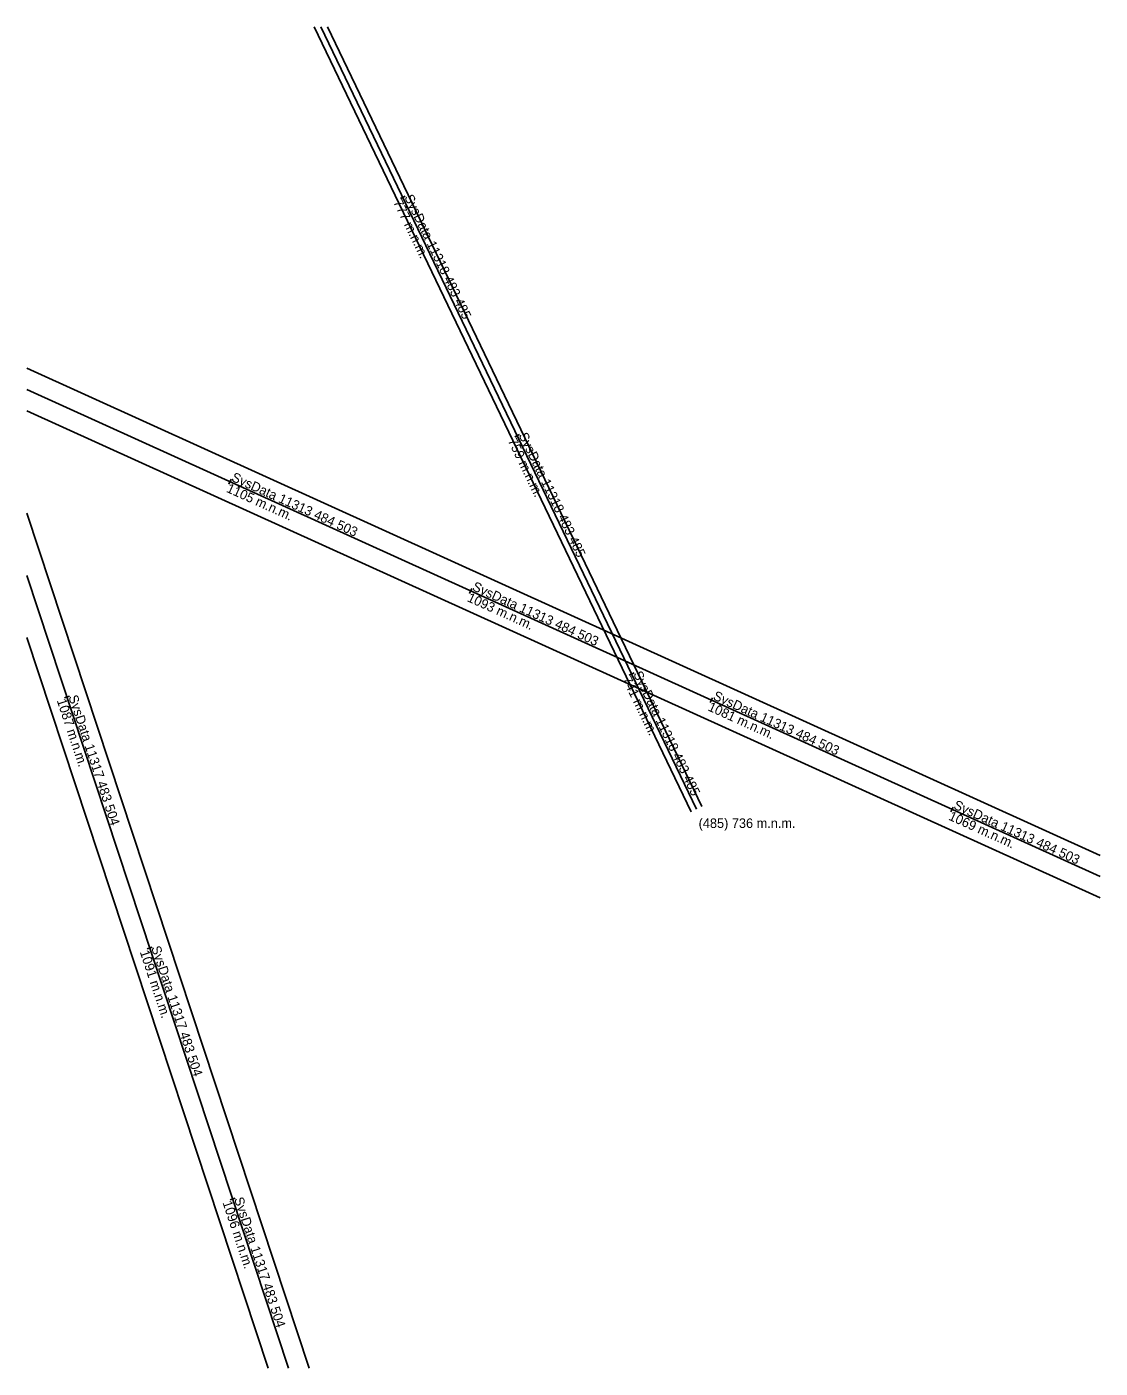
# Model space of a CAD drawing. Extents: x -650309 to -649903, y -983739 to -983231.
import ezdxf

# ---------------------------------------------------------------- set-up
doc = ezdxf.new("R2010")
doc.units = 0
doc.layers.add('Vrstva 1', color=7, linetype='Continuous')

msp = doc.modelspace()

# ---------------------------------------------------------------- linework, layer by layer
at = {"layer": 'Vrstva 1'}
for p, q in [((-650200.49, -983231.28), (-650057.91, -983528.17)), ((-650197.97, -983231.28), (-650055.86, -983527.19)), ((-650195.45, -983231.28), (-650053.81, -983526.21)), ((-650167.89, -983296.23), (-650166.08, -983295.37)), ((-650309.21, -983360.46), (-649903.14, -983544.72)), ((-650309.21, -983368.47), (-649903.14, -983552.74)), ((-650309.21, -983376.49), (-649903.14, -983560.75)), ((-650124.59, -983386.38), (-650122.79, -983385.51)), ((-650231.94, -983402.44), (-650232.77, -983404.26)), ((-650309.21, -983415.27), (-650202.45, -983738.66)), ((-650309.21, -983438.78), (-650210.21, -983738.66)), ((-650140.88, -983443.76), (-650141.71, -983445.58)), ((-650309.21, -983462.28), (-650217.97, -983738.66)), ((-650081.3, -983476.52), (-650079.5, -983475.66)), ((-650294.99, -983485.05), (-650293.09, -983484.42)), ((-650049.82, -983485.08), (-650050.64, -983486.9)), ((-650055.86, -983527.19), (-650055.86, -983527.19)), ((-649958.75, -983526.4), (-649959.58, -983528.23)), ((-650263.64, -983580.01), (-650261.74, -983579.38)), ((-650232.29, -983674.97), (-650230.39, -983674.34))]:
    msp.add_line(p, q, dxfattribs=at)

# ---------------------------------------------------------------- texts
for s, rotation, p in [('777 m.n.m.', 295.6525, (-650170.66, -983297.61)), ('SysData 11318 483 485', 295.6525, (-650166.47, -983295.71)), ('759 m.n.m.', 295.6525, (-650127.33, -983387.85)), ('SysData 11318 483 485', 295.6525, (-650123.22, -983385.77)), ('SysData 11313 484 503', 335.5926, (-650232.11, -983402.91)), ('1105 m.n.m.', 335.5926, (-650233.98, -983407.11)), ('SysData 11313 484 503', 335.5926, (-650140.98, -983444.26)), ('1093 m.n.m.', 335.5926, (-650142.89, -983448.45)), ('741 m.n.m.', 295.6525, (-650084.02, -983478.03)), ('SysData 11318 483 485', 295.6525, (-650079.89, -983476.01)), ('SysData 11317 483 504', 288.2703, (-650293.53, -983484.69)), ('SysData 11313 484 503', 335.5926, (-650049.89, -983485.6)), ('1087 m.n.m.', 288.2703, (-650297.91, -983486.1)), ('1081 m.n.m.', 335.5926, (-650051.82, -983489.77)), ('SysData 11313 484 503', 335.5926, (-649958.92, -983526.88)), ('1069 m.n.m.', 335.5926, (-649960.78, -983531.09)), ('(485) 736 m.n.m.', 0.037, (-650055.06, -983534.32)), ('1091 m.n.m.', 288.2703, (-650266.51, -983581.19)), ('SysData 11317 483 504', 288.2703, (-650262.2, -983579.59)), ('1096 m.n.m.', 288.2703, (-650235.22, -983675.99)), ('SysData 11317 483 504', 288.2703, (-650230.83, -983674.61))]:
    msp.add_text(s, height=3.6, rotation=rotation, dxfattribs=at).set_placement(p)

doc.saveas('drawing.dxf')
